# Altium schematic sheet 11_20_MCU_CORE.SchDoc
size 289 x 396 mm
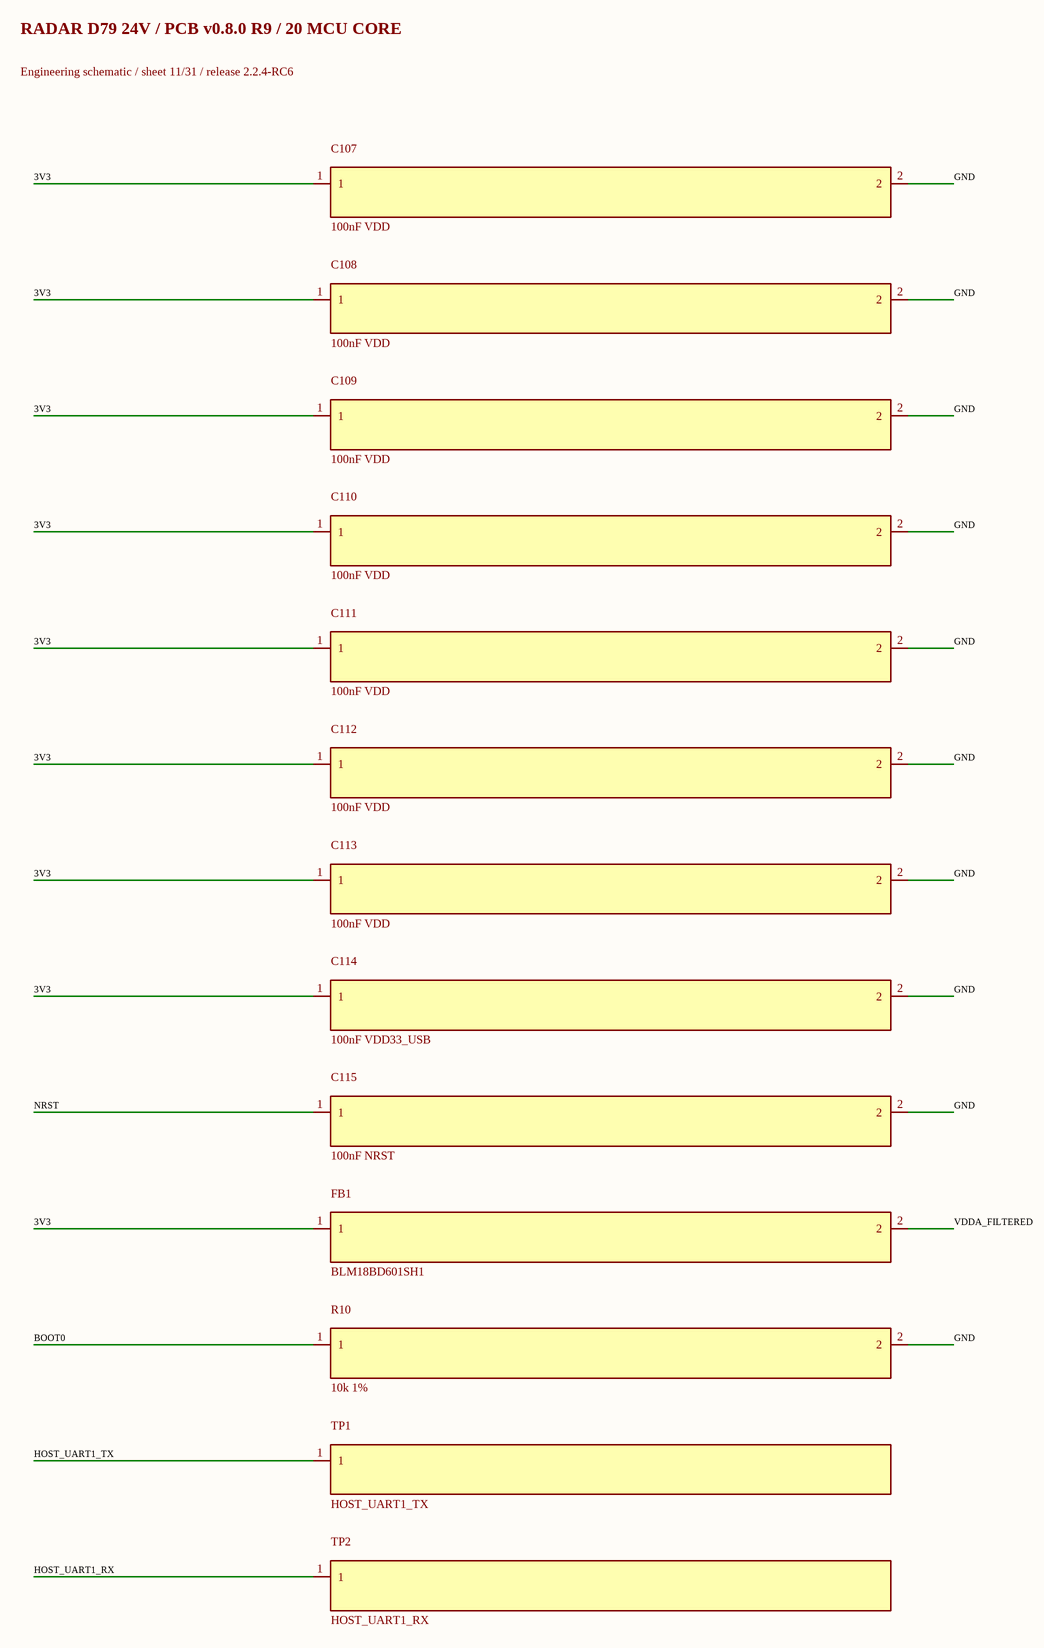
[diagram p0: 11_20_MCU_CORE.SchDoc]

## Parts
C107  100nF VDD  [C_0402_1005Metric]
C108  100nF VDD  [C_0402_1005Metric]
C109  100nF VDD  [C_0402_1005Metric]
C110  100nF VDD  [C_0402_1005Metric]
C111  100nF VDD  [C_0402_1005Metric]
C112  100nF VDD  [C_0402_1005Metric]
C113  100nF VDD  [C_0402_1005Metric]
C114  100nF VDD33_USB  [C_0402_1005Metric]
C115  100nF NRST  [C_0402_1005Metric]
FB1  BLM18BD601SH1  [L_0603_1608Metric]
R10  10k 1%  [R_0603_1608Metric]
TP1  HOST_UART1_TX  [TestPoint_Pad_D1.0mm]
TP2  HOST_UART1_RX  [TestPoint_Pad_D1.0mm]

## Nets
3V3: C107.1 C108.1 C109.1 C110.1 C111.1 C112.1 C113.1 C114.1 FB1.1
BOOT0: R10.1
GND: C107.2 C108.2 C109.2 C110.2 C111.2 C112.2 C113.2 C114.2 C115.2 R10.2
HOST_UART1_RX: TP2.1
HOST_UART1_TX: TP1.1
NRST: C115.1
VDDA_FILTERED: FB1.2

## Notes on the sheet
- RADAR D79 24V / PCB v0.8.0 R9 / 20 MCU CORE
- Engineering schematic / sheet 11/31 / release 2.2.4-RC6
